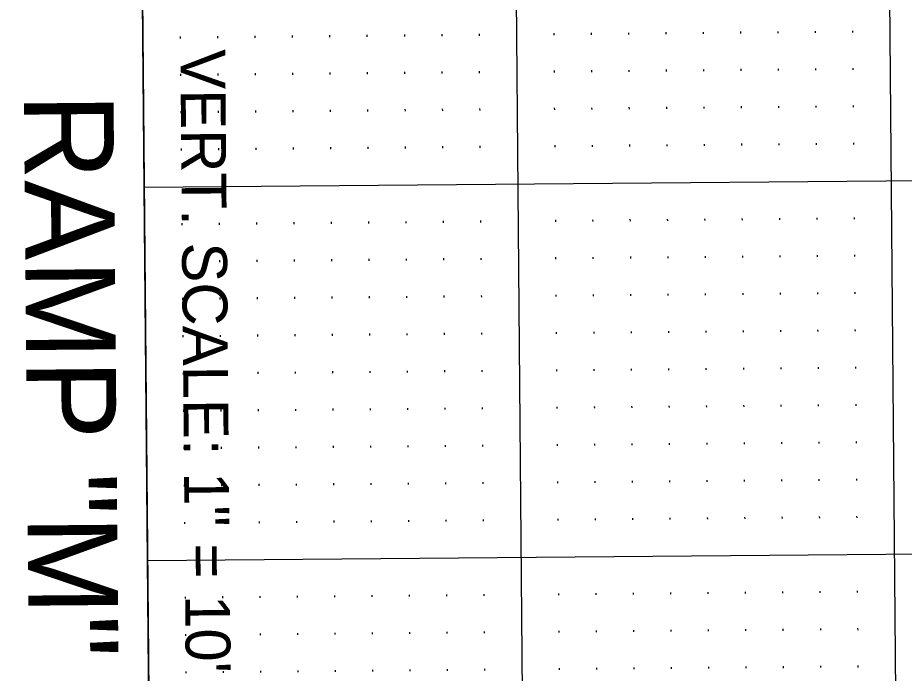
# Model space of a CAD drawing. Extents: x 2149873 to 2152007, y 140538 to 142349.
# Drawn here: x 2150071.4 to 2150190.1, y 140658 to 140745.8 of the extents above; entities that cross this region are included whole.
import ezdxf

# ---------------------------------------------------------------- set-up
doc = ezdxf.new("R2010")
doc.units = 0
for name, color, linetype in [('PR_Align_Ramp_M_Sta', 7, 'Continuous'), ('SHT_Profile_Grid_Major', 7, 'Continuous'), ('SHT_Profile_Grid_Minor', 7, 'Continuous'), ('SHT_Scale', 7, 'Continuous'), ('SHT_Sheet_Border', 7, 'Continuous')]:
    doc.layers.add(name, color=color, linetype=linetype)

msp = doc.modelspace()

# ---------------------------------------------------------------- linework, layer by layer
at = {"layer": 'SHT_Profile_Grid_Major'}
for p, q in [((2150175.72, 142161.38), (2150189.5, 140586.44)), ((2150075.72, 142160.51), (2150089.51, 140585.57)), ((2150125.72, 142160.94), (2150139.51, 140586)), ((2150088.3, 140723.06), (2150488.29, 140726.56)), ((2150088.74, 140673.06), (2150488.73, 140676.56))]:
    msp.add_line(p, q, dxfattribs=at)
at = {"layer": 'SHT_Profile_Grid_Minor'}
for p, q in [((2150163.13, 140743.84), (2150163.13, 140743.59)), ((2150168.13, 140743.89), (2150168.13, 140743.64)), ((2150173.13, 140743.93), (2150173.13, 140743.68)), ((2150178.12, 140743.97), (2150178.13, 140743.72)), ((2150183.12, 140744.02), (2150183.13, 140743.77)), ((2150093.13, 140743.23), (2150093.13, 140742.98)), ((2150098.13, 140743.27), (2150098.13, 140743.02)), ((2150103.13, 140743.32), (2150103.13, 140743.07)), ((2150108.13, 140743.36), (2150108.13, 140743.11)), ((2150113.13, 140743.4), (2150113.13, 140743.15)), ((2150118.13, 140743.45), (2150118.13, 140743.2)), ((2150123.13, 140743.49), (2150123.13, 140743.24)), ((2150128.13, 140743.54), (2150128.13, 140743.29)), ((2150133.13, 140743.58), (2150133.13, 140743.33)), ((2150143.13, 140743.67), (2150143.13, 140743.42)), ((2150148.13, 140743.71), (2150148.13, 140743.46)), ((2150153.13, 140743.75), (2150153.13, 140743.5)), ((2150158.13, 140743.8), (2150158.13, 140743.55)), ((2150093.17, 140738.23), (2150093.17, 140737.98)), ((2150098.17, 140738.27), (2150098.17, 140738.02)), ((2150103.17, 140738.32), (2150103.17, 140738.07)), ((2150108.17, 140738.36), (2150108.17, 140738.11)), ((2150113.17, 140738.4), (2150113.17, 140738.15)), ((2150118.17, 140738.45), (2150118.17, 140738.2)), ((2150123.17, 140738.49), (2150123.17, 140738.24)), ((2150128.17, 140738.54), (2150128.17, 140738.29)), ((2150133.17, 140738.58), (2150133.17, 140738.33)), ((2150143.17, 140738.67), (2150143.17, 140738.42)), ((2150148.17, 140738.71), (2150148.17, 140738.46)), ((2150153.17, 140738.75), (2150153.17, 140738.5)), ((2150158.17, 140738.8), (2150158.17, 140738.55)), ((2150163.17, 140738.84), (2150163.17, 140738.59)), ((2150168.17, 140738.89), (2150168.17, 140738.64)), ((2150173.17, 140738.93), (2150173.17, 140738.68)), ((2150178.17, 140738.97), (2150178.17, 140738.72)), ((2150183.17, 140739.02), (2150183.17, 140738.77)), ((2150093.22, 140733.23), (2150093.22, 140732.98)), ((2150098.22, 140733.27), (2150098.22, 140733.02)), ((2150103.22, 140733.32), (2150103.22, 140733.07)), ((2150108.22, 140733.36), (2150108.22, 140733.11)), ((2150113.21, 140733.4), (2150113.22, 140733.15)), ((2150118.21, 140733.45), (2150118.22, 140733.2)), ((2150123.21, 140733.49), (2150123.22, 140733.24)), ((2150128.21, 140733.54), (2150128.22, 140733.29)), ((2150133.21, 140733.58), (2150133.22, 140733.33)), ((2150143.21, 140733.67), (2150143.22, 140733.42)), ((2150148.21, 140733.71), (2150148.22, 140733.46)), ((2150153.21, 140733.76), (2150153.22, 140733.51)), ((2150158.21, 140733.8), (2150158.22, 140733.55)), ((2150163.21, 140733.84), (2150163.22, 140733.59)), ((2150168.21, 140733.89), (2150168.21, 140733.64)), ((2150173.21, 140733.93), (2150173.21, 140733.68)), ((2150178.21, 140733.97), (2150178.21, 140733.72)), ((2150183.21, 140734.02), (2150183.21, 140733.77)), ((2150113.26, 140728.41), (2150113.26, 140728.16)), ((2150118.26, 140728.45), (2150118.26, 140728.2)), ((2150123.26, 140728.49), (2150123.26, 140728.24)), ((2150128.26, 140728.54), (2150128.26, 140728.29)), ((2150133.26, 140728.58), (2150133.26, 140728.33)), ((2150143.26, 140728.67), (2150143.26, 140728.42)), ((2150148.26, 140728.71), (2150148.26, 140728.46)), ((2150153.26, 140728.76), (2150153.26, 140728.51)), ((2150158.26, 140728.8), (2150158.26, 140728.55)), ((2150163.26, 140728.84), (2150163.26, 140728.59)), ((2150168.26, 140728.89), (2150168.26, 140728.64)), ((2150173.26, 140728.93), (2150173.26, 140728.68)), ((2150178.26, 140728.97), (2150178.26, 140728.72)), ((2150183.26, 140729.02), (2150183.26, 140728.77)), ((2150093.26, 140728.23), (2150093.26, 140727.98)), ((2150098.26, 140728.27), (2150098.26, 140728.02)), ((2150103.26, 140728.32), (2150103.26, 140728.07)), ((2150108.26, 140728.36), (2150108.26, 140728.11)), ((2150168.34, 140718.89), (2150168.35, 140718.64)), ((2150173.34, 140718.93), (2150173.35, 140718.68)), ((2150178.34, 140718.97), (2150178.35, 140718.72)), ((2150183.34, 140719.02), (2150183.35, 140718.77)), ((2150093.35, 140718.23), (2150093.35, 140717.98)), ((2150098.35, 140718.27), (2150098.35, 140718.02)), ((2150103.35, 140718.32), (2150103.35, 140718.07)), ((2150108.35, 140718.36), (2150108.35, 140718.11)), ((2150113.35, 140718.41), (2150113.35, 140718.16)), ((2150118.35, 140718.45), (2150118.35, 140718.2)), ((2150123.35, 140718.49), (2150123.35, 140718.24)), ((2150128.35, 140718.54), (2150128.35, 140718.29)), ((2150133.35, 140718.58), (2150133.35, 140718.33)), ((2150143.35, 140718.67), (2150143.35, 140718.42)), ((2150148.34, 140718.71), (2150148.35, 140718.46)), ((2150153.34, 140718.76), (2150153.35, 140718.51)), ((2150158.34, 140718.8), (2150158.35, 140718.55)), ((2150163.34, 140718.84), (2150163.35, 140718.59)), ((2150093.39, 140713.23), (2150093.39, 140712.98)), ((2150098.39, 140713.27), (2150098.39, 140713.02)), ((2150103.39, 140713.32), (2150103.39, 140713.07)), ((2150108.39, 140713.36), (2150108.39, 140713.11)), ((2150113.39, 140713.41), (2150113.39, 140713.16)), ((2150118.39, 140713.45), (2150118.39, 140713.2)), ((2150123.39, 140713.49), (2150123.39, 140713.24)), ((2150128.39, 140713.54), (2150128.39, 140713.29)), ((2150133.39, 140713.58), (2150133.39, 140713.33)), ((2150143.39, 140713.67), (2150143.39, 140713.42)), ((2150148.39, 140713.71), (2150148.39, 140713.46)), ((2150153.39, 140713.76), (2150153.39, 140713.51)), ((2150158.39, 140713.8), (2150158.39, 140713.55)), ((2150163.39, 140713.84), (2150163.39, 140713.59)), ((2150168.39, 140713.89), (2150168.39, 140713.64)), ((2150173.39, 140713.93), (2150173.39, 140713.68)), ((2150178.39, 140713.97), (2150178.39, 140713.72)), ((2150183.39, 140714.02), (2150183.39, 140713.77)), ((2150093.43, 140708.23), (2150093.44, 140707.98)), ((2150098.43, 140708.27), (2150098.44, 140708.02)), ((2150103.43, 140708.32), (2150103.44, 140708.07)), ((2150108.43, 140708.36), (2150108.44, 140708.11)), ((2150113.43, 140708.41), (2150113.44, 140708.16)), ((2150118.43, 140708.45), (2150118.44, 140708.2)), ((2150123.43, 140708.49), (2150123.44, 140708.24)), ((2150128.43, 140708.54), (2150128.44, 140708.29)), ((2150133.43, 140708.58), (2150133.44, 140708.33)), ((2150143.43, 140708.67), (2150143.43, 140708.42)), ((2150148.43, 140708.71), (2150148.43, 140708.46)), ((2150153.43, 140708.76), (2150153.43, 140708.51)), ((2150158.43, 140708.8), (2150158.43, 140708.55)), ((2150163.43, 140708.84), (2150163.43, 140708.59)), ((2150168.43, 140708.89), (2150168.43, 140708.64)), ((2150173.43, 140708.93), (2150173.43, 140708.68)), ((2150178.43, 140708.97), (2150178.43, 140708.72)), ((2150183.43, 140709.02), (2150183.43, 140708.77)), ((2150118.48, 140703.45), (2150118.48, 140703.2)), ((2150123.48, 140703.49), (2150123.48, 140703.24)), ((2150128.48, 140703.54), (2150128.48, 140703.29)), ((2150133.48, 140703.58), (2150133.48, 140703.33)), ((2150143.48, 140703.67), (2150143.48, 140703.42)), ((2150148.48, 140703.71), (2150148.48, 140703.46)), ((2150153.48, 140703.76), (2150153.48, 140703.51)), ((2150158.48, 140703.8), (2150158.48, 140703.55)), ((2150163.48, 140703.84), (2150163.48, 140703.59)), ((2150168.48, 140703.89), (2150168.48, 140703.64)), ((2150173.48, 140703.93), (2150173.48, 140703.68)), ((2150178.47, 140703.98), (2150178.48, 140703.73)), ((2150183.47, 140704.02), (2150183.48, 140703.77)), ((2150093.48, 140703.23), (2150093.48, 140702.98)), ((2150098.48, 140703.27), (2150098.48, 140703.02)), ((2150103.48, 140703.32), (2150103.48, 140703.07)), ((2150108.48, 140703.36), (2150108.48, 140703.11)), ((2150113.48, 140703.41), (2150113.48, 140703.16)), ((2150148.52, 140698.71), (2150148.52, 140698.46)), ((2150153.52, 140698.76), (2150153.52, 140698.51)), ((2150158.52, 140698.8), (2150158.52, 140698.55)), ((2150163.52, 140698.84), (2150163.52, 140698.59)), ((2150168.52, 140698.89), (2150168.52, 140698.64)), ((2150173.52, 140698.93), (2150173.52, 140698.68)), ((2150178.52, 140698.98), (2150178.52, 140698.73)), ((2150183.52, 140699.02), (2150183.52, 140698.77)), ((2150093.52, 140698.23), (2150093.52, 140697.98)), ((2150098.52, 140698.27), (2150098.52, 140698.02)), ((2150103.52, 140698.32), (2150103.52, 140698.07)), ((2150108.52, 140698.36), (2150108.52, 140698.11)), ((2150113.52, 140698.41), (2150113.52, 140698.16)), ((2150118.52, 140698.45), (2150118.52, 140698.2)), ((2150123.52, 140698.49), (2150123.52, 140698.24)), ((2150128.52, 140698.54), (2150128.52, 140698.29)), ((2150133.52, 140698.58), (2150133.52, 140698.33)), ((2150143.52, 140698.67), (2150143.52, 140698.42)), ((2150178.56, 140693.98), (2150178.56, 140693.73)), ((2150183.56, 140694.02), (2150183.56, 140693.77)), ((2150093.57, 140693.23), (2150093.57, 140692.98)), ((2150098.57, 140693.28), (2150098.57, 140693.03)), ((2150103.57, 140693.32), (2150103.57, 140693.07)), ((2150108.57, 140693.36), (2150108.57, 140693.11)), ((2150113.57, 140693.41), (2150113.57, 140693.16)), ((2150118.56, 140693.45), (2150118.57, 140693.2)), ((2150123.56, 140693.49), (2150123.57, 140693.24)), ((2150128.56, 140693.54), (2150128.57, 140693.29)), ((2150133.56, 140693.58), (2150133.57, 140693.33)), ((2150143.56, 140693.67), (2150143.57, 140693.42)), ((2150148.56, 140693.71), (2150148.57, 140693.46)), ((2150153.56, 140693.76), (2150153.57, 140693.51)), ((2150158.56, 140693.8), (2150158.57, 140693.55)), ((2150163.56, 140693.84), (2150163.57, 140693.59)), ((2150168.56, 140693.89), (2150168.57, 140693.64)), ((2150173.56, 140693.93), (2150173.56, 140693.68)), ((2150093.61, 140688.23), (2150093.61, 140687.98)), ((2150098.61, 140688.28), (2150098.61, 140688.03)), ((2150103.61, 140688.32), (2150103.61, 140688.07)), ((2150108.61, 140688.36), (2150108.61, 140688.11)), ((2150113.61, 140688.41), (2150113.61, 140688.16)), ((2150118.61, 140688.45), (2150118.61, 140688.2)), ((2150123.61, 140688.49), (2150123.61, 140688.24)), ((2150128.61, 140688.54), (2150128.61, 140688.29)), ((2150133.61, 140688.58), (2150133.61, 140688.33)), ((2150143.61, 140688.67), (2150143.61, 140688.42)), ((2150148.61, 140688.71), (2150148.61, 140688.46)), ((2150153.61, 140688.76), (2150153.61, 140688.51)), ((2150158.61, 140688.8), (2150158.61, 140688.55)), ((2150163.61, 140688.84), (2150163.61, 140688.59)), ((2150168.61, 140688.89), (2150168.61, 140688.64)), ((2150173.61, 140688.93), (2150173.61, 140688.68)), ((2150178.61, 140688.98), (2150178.61, 140688.73)), ((2150183.61, 140689.02), (2150183.61, 140688.77)), ((2150098.65, 140683.28), (2150098.66, 140683.03)), ((2150103.65, 140683.32), (2150103.66, 140683.07)), ((2150108.65, 140683.36), (2150108.65, 140683.11)), ((2150113.65, 140683.41), (2150113.65, 140683.16)), ((2150118.65, 140683.45), (2150118.65, 140683.2)), ((2150123.65, 140683.49), (2150123.65, 140683.24)), ((2150128.65, 140683.54), (2150128.65, 140683.29)), ((2150133.65, 140683.58), (2150133.65, 140683.33)), ((2150143.65, 140683.67), (2150143.65, 140683.42)), ((2150148.65, 140683.71), (2150148.65, 140683.46)), ((2150153.65, 140683.76), (2150153.65, 140683.51)), ((2150158.65, 140683.8), (2150158.65, 140683.55)), ((2150163.65, 140683.84), (2150163.65, 140683.59)), ((2150168.65, 140683.89), (2150168.65, 140683.64)), ((2150173.65, 140683.93), (2150173.65, 140683.68)), ((2150178.65, 140683.98), (2150178.65, 140683.73)), ((2150183.65, 140684.02), (2150183.65, 140683.77)), ((2150093.65, 140683.23), (2150093.66, 140682.98)), ((2150128.7, 140678.54), (2150128.7, 140678.29)), ((2150133.7, 140678.58), (2150133.7, 140678.33)), ((2150143.7, 140678.67), (2150143.7, 140678.42)), ((2150148.7, 140678.71), (2150148.7, 140678.46)), ((2150153.69, 140678.76), (2150153.7, 140678.51)), ((2150158.69, 140678.8), (2150158.7, 140678.55)), ((2150163.69, 140678.84), (2150163.7, 140678.59)), ((2150168.69, 140678.89), (2150168.7, 140678.64)), ((2150173.69, 140678.93), (2150173.7, 140678.68)), ((2150178.69, 140678.98), (2150178.7, 140678.73)), ((2150183.69, 140679.02), (2150183.7, 140678.77)), ((2150093.7, 140678.23), (2150093.7, 140677.98)), ((2150098.7, 140678.28), (2150098.7, 140678.03)), ((2150103.7, 140678.32), (2150103.7, 140678.07)), ((2150108.7, 140678.36), (2150108.7, 140678.11)), ((2150113.7, 140678.41), (2150113.7, 140678.16)), ((2150118.7, 140678.45), (2150118.7, 140678.2)), ((2150123.7, 140678.49), (2150123.7, 140678.24)), ((2150183.78, 140669.02), (2150183.78, 140668.77)), ((2150093.78, 140668.23), (2150093.79, 140667.98)), ((2150098.78, 140668.28), (2150098.79, 140668.03)), ((2150103.78, 140668.32), (2150103.79, 140668.07)), ((2150108.78, 140668.36), (2150108.79, 140668.11)), ((2150113.78, 140668.41), (2150113.79, 140668.16)), ((2150118.78, 140668.45), (2150118.79, 140668.2)), ((2150123.78, 140668.49), (2150123.79, 140668.24)), ((2150128.78, 140668.54), (2150128.79, 140668.29)), ((2150133.78, 140668.58), (2150133.79, 140668.33)), ((2150143.78, 140668.67), (2150143.78, 140668.42)), ((2150148.78, 140668.71), (2150148.78, 140668.46)), ((2150153.78, 140668.76), (2150153.78, 140668.51)), ((2150158.78, 140668.8), (2150158.78, 140668.55)), ((2150163.78, 140668.85), (2150163.78, 140668.6)), ((2150168.78, 140668.89), (2150168.78, 140668.64)), ((2150173.78, 140668.93), (2150173.78, 140668.68)), ((2150178.78, 140668.98), (2150178.78, 140668.73)), ((2150093.83, 140663.23), (2150093.83, 140662.98)), ((2150098.83, 140663.28), (2150098.83, 140663.03)), ((2150103.83, 140663.32), (2150103.83, 140663.07)), ((2150108.83, 140663.36), (2150108.83, 140663.11)), ((2150113.83, 140663.41), (2150113.83, 140663.16)), ((2150118.83, 140663.45), (2150118.83, 140663.2)), ((2150123.83, 140663.5), (2150123.83, 140663.25)), ((2150128.83, 140663.54), (2150128.83, 140663.29)), ((2150133.83, 140663.58), (2150133.83, 140663.33)), ((2150143.83, 140663.67), (2150143.83, 140663.42)), ((2150148.83, 140663.71), (2150148.83, 140663.46)), ((2150153.83, 140663.76), (2150153.83, 140663.51)), ((2150158.83, 140663.8), (2150158.83, 140663.55)), ((2150163.83, 140663.85), (2150163.83, 140663.6)), ((2150168.83, 140663.89), (2150168.83, 140663.64)), ((2150173.83, 140663.93), (2150173.83, 140663.68)), ((2150178.83, 140663.98), (2150178.83, 140663.73)), ((2150183.82, 140664.02), (2150183.83, 140663.77)), ((2150108.87, 140658.36), (2150108.87, 140658.11)), ((2150113.87, 140658.41), (2150113.87, 140658.16)), ((2150118.87, 140658.45), (2150118.87, 140658.2)), ((2150123.87, 140658.5), (2150123.87, 140658.25)), ((2150128.87, 140658.54), (2150128.87, 140658.29)), ((2150133.87, 140658.58), (2150133.87, 140658.33)), ((2150143.87, 140658.67), (2150143.87, 140658.42)), ((2150148.87, 140658.71), (2150148.87, 140658.46)), ((2150153.87, 140658.76), (2150153.87, 140658.51)), ((2150158.87, 140658.8), (2150158.87, 140658.55)), ((2150163.87, 140658.85), (2150163.87, 140658.6)), ((2150168.87, 140658.89), (2150168.87, 140658.64)), ((2150173.87, 140658.93), (2150173.87, 140658.68)), ((2150178.87, 140658.98), (2150178.87, 140658.73)), ((2150183.87, 140659.02), (2150183.87, 140658.77)), ((2150093.87, 140658.23), (2150093.87, 140657.98)), ((2150098.87, 140658.28), (2150098.87, 140658.03)), ((2150103.87, 140658.32), (2150103.87, 140658.07))]:
    msp.add_line(p, q, dxfattribs=at)
at = {"layer": 'SHT_Sheet_Border'}
msp.add_lwpolyline([(2150087.87, 140773.06), (2150067.87, 140772.88), (2150069.18, 140622.89), (2150089.18, 140623.07)], close=True, dxfattribs=at)

# ---------------------------------------------------------------- texts
at = {"layer": 'PR_Align_Ramp_M_Sta'}
msp.add_text('RAMP "M"', height=12, rotation=270.5015, dxfattribs=at).set_placement((2150072.19, 140735.59))
at = {"layer": 'SHT_Scale'}
msp.add_text('VERT. SCALE: 1" = 10\'', height=6, rotation=270.5015, dxfattribs=at).set_placement((2150093.14, 140741.5))

doc.saveas('drawing.dxf')
